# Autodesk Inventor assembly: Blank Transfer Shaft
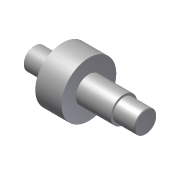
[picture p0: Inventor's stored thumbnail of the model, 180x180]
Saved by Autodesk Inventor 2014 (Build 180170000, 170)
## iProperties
Created: 2011-01
Part Number: Blank Transfer Shaft
Document SubType Name: Assembly
Designer: Beta-8540w
ClientObjectVersion: 1
Author: Beta-8540w
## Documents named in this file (2)
- C:\Inventor 2014 Essentials\Assemblies\Chapter 09\Design Accelerators\Blank Transfer Shaft.iam
- C:\Inventor 2014 Essentials\Assemblies\Chapter 09\Design Accelerators\Blank Transfer Shaft.ipt
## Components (1 placed, 1 different names)
1. Blank Transfer Shaft:1
